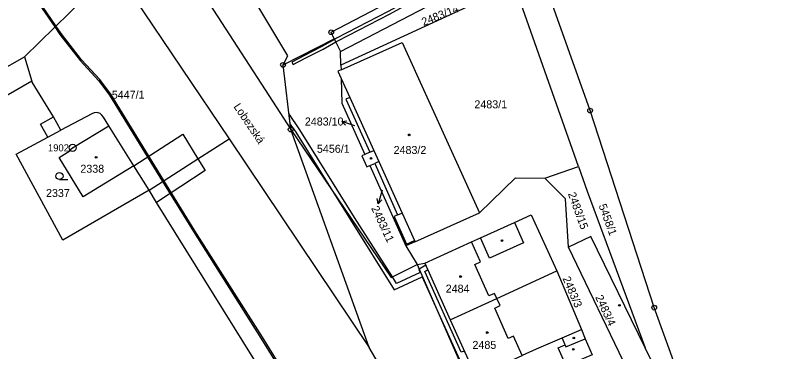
# Model space of a CAD drawing. Extents: x -821458 to -820266, y -1071458 to -1069826.
# Drawn here: x -820846.6 to -820683.2, y -1071063.4 to -1070992 of the extents above; entities that cross this region are included whole.
import ezdxf

# ---------------------------------------------------------------- set-up
doc = ezdxf.new("R2010")
doc.units = 0
for name, color, linetype in [('Vrstva 1', 7, 'Continuous'), ('Vrstva 13', 7, 'Continuous'), ('Vrstva 2', 7, 'Continuous'), ('Vrstva 3', 7, 'Continuous'), ('Vrstva 4', 7, 'Continuous'), ('Vrstva 5', 7, 'Continuous'), ('Vrstva 7', 7, 'Continuous'), ('Vrstva 8', 7, 'Continuous')]:
    doc.layers.add(name, color=color, linetype=linetype)

msp = doc.modelspace()

# ---------------------------------------------------------------- linework, layer by layer
at = {"layer": 'Vrstva 1'}
for p, q in [((-820777.53, -1070999.61), (-820742.13, -1070981.22)), ((-820824.34, -1070983.84), (-820801.18, -1071018.22)), ((-820740.61, -1070985.51), (-820777.45, -1071002.55)), ((-820726.97, -1071024.08), (-820740.61, -1070985.51)), ((-820789.77, -1071002.5), (-820778.87, -1070996.92)), ((-820778.87, -1070996.92), (-820777.53, -1070999.61)), ((-820919.49, -1071043.49), (-820844.72, -1071000.76)), ((-820844.72, -1071000.76), (-820843.13, -1071005.97)), ((-820777.45, -1071002.55), (-820777.53, -1070999.61)), ((-820788.14, -1071016.23), (-820789.77, -1071002.5)), ((-820777.45, -1071002.55), (-820777.43, -1071003.51)), ((-820821.47, -1071023.96), (-820826.78, -1071015.45)), ((-820771.44, -1071062.55), (-820788.14, -1071016.23)), ((-820801.18, -1071018.22), (-820771.44, -1071062.55)), ((-820818.18, -1071029.09), (-820821.47, -1071023.96)), ((-820771.32, -1071023.9), (-820763.7, -1071040.96)), ((-820734.1, -1071026.6), (-820726.97, -1071024.08)), ((-820761.74, -1071040.08), (-820748.04, -1071033.93)), ((-820761.74, -1071040.08), (-820763.7, -1071040.96)), ((-820763.7, -1071040.96), (-820761.23, -1071044.95)), ((-820714.94, -1071070.69), (-820729.09, -1071041.23)), ((-820761.23, -1071044.95), (-820759.64, -1071044.63)), ((-820759.64, -1071044.63), (-820754.22, -1071056.69)), ((-820731.61, -1071046.26), (-820726.37, -1071058.75)), ((-820754.22, -1071056.69), (-820748.77, -1071068.73)), ((-820730.46, -1071060.52), (-820726.37, -1071058.75))]:
    msp.add_line(p, q, dxfattribs=at)
for points in [[(-820849.37, -1070921.6), (-820793.59, -1071007.77), (-820788.14, -1071016.23)], [(-820789.77, -1071002.5), (-820788.75, -1071000.53), (-820808.02, -1070968.42)], [(-820669.33, -1071161.28), (-820683.15, -1071130.16), (-820686.65, -1071120.86), (-820710.89, -1071054.09), (-820724.52, -1071012.19), (-820736.51, -1070978.31)], [(-820844.72, -1071000.76), (-820828.74, -1070985.09), (-820824.34, -1070983.84)], [(-820778.87, -1070996.92), (-820779.53, -1070995.55), (-820769.46, -1070990.29)], [(-820777.43, -1071003.51), (-820764.47, -1070997.74), (-820748.04, -1071033.93)], [(-820777.43, -1071003.51), (-820778.1, -1071003.81), (-820777.38, -1071005.4)], [(-820843.13, -1071005.97), (-820851.45, -1071010.71), (-820862.03, -1071016.55), (-820868.3, -1071020.34)], [(-820836.97, -1071016.39), (-820838.57, -1071013.55), (-820843.06, -1071006.19), (-820843.13, -1071005.97)], [(-820777.38, -1071005.4), (-820777.26, -1071010.6), (-820772.38, -1071021.52)], [(-820777.38, -1071005.4), (-820775.57, -1071009.41), (-820776.45, -1071009.77), (-820771.33, -1071021.06), (-820772.38, -1071021.52)], [(-820826.78, -1071015.45), (-820827.94, -1071013.59), (-820828.25, -1071013.16), (-820828.63, -1071012.82), (-820829.23, -1071012.63), (-820829.89, -1071012.67), (-820830.41, -1071012.91), (-820836.97, -1071016.39)], [(-820821.47, -1071023.96), (-820832.21, -1071030.56), (-820837.33, -1071022.15), (-820835.08, -1071020.75), (-820835.16, -1071020.62), (-820834.47, -1071020.12), (-820826.78, -1071015.45)], [(-820818.18, -1071029.09), (-820836.59, -1071039.77), (-820846.48, -1071021.44), (-820839.73, -1071017.86), (-820836.97, -1071016.39)], [(-820788.14, -1071016.23), (-820766.82, -1071047.7), (-820761.23, -1071044.95)], [(-820818.18, -1071029.09), (-820807.85, -1071022.43), (-820801.18, -1071018.22)], [(-820772.38, -1071021.52), (-820773.03, -1071021.8), (-820771.93, -1071024.17), (-820771.32, -1071023.9)], [(-820771.32, -1071023.9), (-820770.29, -1071023.43), (-820765.41, -1071034.38), (-820766.17, -1071034.7), (-820763.51, -1071040.59), (-820761.84, -1071039.85), (-820761.74, -1071040.08)], [(-820726.97, -1071024.08), (-820725.12, -1071029.32), (-820712.83, -1071062.62)], [(-820748.04, -1071033.93), (-820740.34, -1071026.47), (-820734.1, -1071026.6)], [(-820729.09, -1071041.23), (-820729.72, -1071030.98), (-820734.1, -1071026.6)], [(-820767.3, -1071111.07), (-820816.68, -1071031.77), (-820818.18, -1071029.09)], [(-820759.64, -1071044.63), (-820749.7, -1071040.13), (-820747.77, -1071039.26), (-820740.58, -1071036), (-820737.02, -1071034.39), (-820731.61, -1071046.26)], [(-820712.83, -1071062.62), (-820724.39, -1071038.93), (-820729.09, -1071041.23)], [(-820761.23, -1071044.95), (-820734.74, -1071105.53), (-820721.97, -1071129.66), (-820703.01, -1071165.5), (-820691.2, -1071188.61), (-820680.04, -1071206.39)], [(-820754.22, -1071056.69), (-820744.33, -1071052.15), (-820731.61, -1071046.26)], [(-820726.37, -1071058.75), (-820725.55, -1071060.69), (-820724.1, -1071064.14)], [(-820748.77, -1071068.73), (-820738.95, -1071064.23), (-820738.86, -1071064.19), (-820735.92, -1071062.86), (-820730.46, -1071060.52)], [(-820724.1, -1071064.14), (-820729.63, -1071066.49), (-820731.27, -1071062.63), (-820729.83, -1071062.02), (-820730.46, -1071060.52)], [(-820739.11, -1071120.37), (-820747.86, -1071108.32), (-820753.77, -1071098.92), (-820763.61, -1071075.96), (-820771.44, -1071062.55)], [(-820710.62, -1071068.59), (-820710.05, -1071068.31), (-820712.83, -1071062.62)]]:
    msp.add_lwpolyline(points, dxfattribs=at)
at = {"layer": 'Vrstva 13'}
for points in [[(-820785.08, -1071001.08), (-820781.23, -1070999.13), (-820778.53, -1070997.6), (-820778.12, -1070997.36), (-820767.13, -1070991.68), (-820757.55, -1070986.38), (-820751.2, -1070982.67), (-820743.93, -1070978.21), (-820741.88, -1070977.07), (-820742.19, -1070976.05), (-820742.73, -1070976.34), (-820742.6, -1070976.79), (-820744.23, -1070977.69), (-820751.5, -1070982.15), (-820757.85, -1070985.86), (-820767.41, -1070991.16), (-820778.4, -1070996.84), (-820778.8, -1070997.06), (-820781.51, -1070998.61), (-820785.36, -1071000.54), (-820787.88, -1071001.9), (-820787.6, -1071002.42)], [(-820768.15, -1071103.3), (-820767.85, -1071103.12), (-820779.29, -1071084.34), (-820794.15, -1071060.39), (-820808.48, -1071037.73), (-820815.06, -1071027.08), (-820826.38, -1071008.73), (-820828.7, -1071005.59), (-820832.57, -1071001.42), (-820836.89, -1070995.8), (-820838.01, -1070994.18), (-820844.65, -1070984.51), (-820844.95, -1070984.68), (-820838.26, -1070994.42), (-820837.17, -1070996), (-820832.83, -1071001.64), (-820828.97, -1071005.81), (-820826.67, -1071008.93), (-820815.35, -1071027.27), (-820808.78, -1071037.91), (-820794.45, -1071060.57), (-820779.59, -1071084.52)]]:
    msp.add_lwpolyline(points, close=True, dxfattribs=at)
for points in [[(-820786.23, -1071016.26), (-820788.55, -1071012.81), (-820788.29, -1071014.99), (-820787.07, -1071016.8), (-820778.99, -1071029.73), (-820775.42, -1071035.45), (-820766.12, -1071050.28), (-820760.23, -1071047.52), (-820756.43, -1071055.93), (-820750.24, -1071069.65), (-820743.37, -1071084.86), (-820734.39, -1071104.82), (-820715.9, -1071140.51), (-820706.2, -1071159.17), (-820691.74, -1071187.18), (-820690.76, -1071187.86), (-820687.33, -1071192.87), (-820680.2, -1071204.48), (-820676.58, -1071209.98), (-820677.42, -1071210.57), (-820671.47, -1071220.04)], [(-820750.81, -1071064.23), (-820751.22, -1071063.31), (-820751.89, -1071063.56), (-820759.65, -1071046.37), (-820759.03, -1071045.99), (-820759.44, -1071045.07), (-820760.81, -1071045.9), (-820760.93, -1071045.97), (-820760.64, -1071046.61), (-820765.65, -1071048.95), (-820766.53, -1071047.56), (-820774.58, -1071034.91), (-820786.23, -1071016.26)]]:
    msp.add_lwpolyline(points, dxfattribs=at)
at = {"layer": 'Vrstva 3'}
msp.add_line((-820837.27, -1071026.87), (-820835.52, -1071026.87), dxfattribs=at)
msp.add_circle((-820837.27, -1071026.12), 0.75, dxfattribs=at)
at = {"layer": 'Vrstva 4'}
for p, q in [((-820775.57, -1071009.41), (-820770.48, -1071020.69)), ((-820841.32, -1071015.09), (-820838.57, -1071013.55)), ((-820839.73, -1071017.86), (-820841.32, -1071015.09)), ((-820821.47, -1071023.96), (-820811.07, -1071017.21)), ((-820811.07, -1071017.21), (-820807.85, -1071022.43)), ((-820771.33, -1071021.06), (-820770.48, -1071020.69)), ((-820770.48, -1071020.69), (-820769.43, -1071023.04)), ((-820807.85, -1071022.43), (-820806.3, -1071024.96)), ((-820769.43, -1071023.04), (-820770.29, -1071023.43)), ((-820769.43, -1071023.04), (-820764.48, -1071033.99)), ((-820806.3, -1071024.96), (-820816.68, -1071031.77)), ((-820765.41, -1071034.38), (-820764.48, -1071033.99)), ((-820764.48, -1071033.99), (-820761.84, -1071039.85)), ((-820740.58, -1071036), (-820738.69, -1071040.33)), ((-820747.8, -1071044.37), (-820749.7, -1071040.13)), ((-820745.86, -1071043.59), (-820747.77, -1071039.26)), ((-820738.69, -1071040.33), (-820745.86, -1071043.59)), ((-820749.01, -1071044.91), (-820747.8, -1071044.37)), ((-820746.03, -1071051.59), (-820749.01, -1071044.91)), ((-820744.82, -1071051.05), (-820746.03, -1071051.59)), ((-820744.33, -1071052.15), (-820744.82, -1071051.05)), ((-820743.63, -1071053.65), (-820744.33, -1071052.15)), ((-820744.79, -1071054.19), (-820743.63, -1071053.65)), ((-820741.94, -1071060.67), (-820744.79, -1071054.19)), ((-820740.77, -1071060.15), (-820741.94, -1071060.67)), ((-820738.95, -1071064.23), (-820740.77, -1071060.15)), ((-820729.66, -1071062.42), (-820725.55, -1071060.69)), ((-820729.83, -1071062.02), (-820729.66, -1071062.42))]:
    msp.add_line(p, q, dxfattribs=at)
at = {"layer": 'Vrstva 5'}
for centre in [(-820762.95, -1071017.37), (-820829.48, -1071022.14), (-820771.09, -1071022.38), (-820743.23, -1071039.83), (-820752.04, -1071047.48), (-820718.27, -1071053.59), (-820746.38, -1071059.38), (-820727.97, -1071060.53), (-820728.08, -1071062.95)]:
    msp.add_circle(centre, 0.175, dxfattribs=at)
at = {"layer": 'Vrstva 7'}
for p, q in [((-820777.25, -1071014.5), (-820776.18, -1071014.36)), ((-820774.5, -1071015.45), (-820777.25, -1071014.5)), ((-820777.25, -1071014.5), (-820776.49, -1071015.28)), ((-820768.69, -1071029.14), (-820769.57, -1071032.01)), ((-820768.68, -1071029.1), (-820768.69, -1071029.14)), ((-820769.57, -1071032.01), (-820769.75, -1071030.91)), ((-820769.57, -1071032.01), (-820768.8, -1071031.2))]:
    msp.add_line(p, q, dxfattribs=at)
at = {"layer": 'Vrstva 8'}
for centre, radius in [((-820779.53, -1070995.55), 0.5), ((-820779.53, -1070995.55), 0.0303), ((-820789.77, -1071002.5), 0.5), ((-820789.77, -1071002.5), 0.0303), ((-820724.52, -1071012.19), 0.5), ((-820724.52, -1071012.19), 0.0303), ((-820788.14, -1071016.23), 0.5), ((-820788.14, -1071016.23), 0.0303), ((-820834.47, -1071020.12), 0.75), ((-820834.47, -1071020.12), 0.03), ((-820710.89, -1071054.09), 0.5), ((-820710.89, -1071054.09), 0.0303)]:
    msp.add_circle(centre, radius, dxfattribs=at)

# ---------------------------------------------------------------- texts
at = {"layer": 'Vrstva 2'}
for s, rotation, p in [('2483/14', 22, (-820759.91, -1070994.23)), ('2483/15', 290, (-820729.25, -1071029.89)), ('5458/1', 290, (-820722.73, -1071032.39)), ('2483/11', 295, (-820771.07, -1071032.94)), ('2483/3', 293, (-820730.4, -1071047.87)), ('2483/4', 295, (-820723.46, -1071051.87))]:
    msp.add_text(s, height=1.7, rotation=rotation, dxfattribs=at).set_placement(p)
for s, p in [('5447/1', (-820826.15, -1071009.67)), ('2483/1', (-820749.1, -1071011.72)), ('2483/10', (-820785.13, -1071015.37)), ('5456/1', (-820782.56, -1071021.17)), ('2483/2', (-820766.27, -1071021.42)), ('2338', (-820832.83, -1071025.41)), ('2337', (-820840.13, -1071030.57)), ('2484', (-820755.2, -1071050.9)), ('2485', (-820749.51, -1071062.86))]:
    msp.add_text(s, height=1.7, dxfattribs=at).set_placement(p)
at = {"layer": 'Vrstva 7'}
msp.add_text('Lobezská', height=1.7, rotation=304, dxfattribs=at).set_placement((-820800.36, -1071011.36))
at = {"layer": 'Vrstva 8'}
msp.add_text('1902', height=1.5, dxfattribs=at).set_placement((-820839.72, -1071020.87))

doc.saveas('drawing.dxf')
